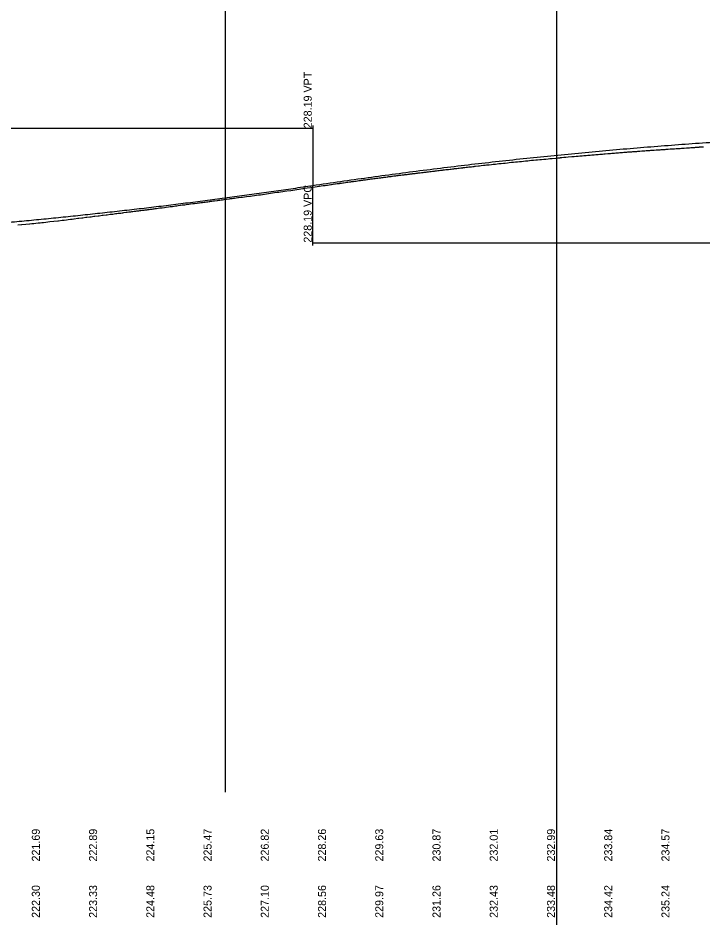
# Model space of a CAD drawing. Extents: x 1838386 to 1955906, y 719739 to 834437.
# Drawn here: x 1889393 to 1889991, y 825634 to 826420 of the extents above; entities that cross this region are included whole.
import ezdxf

# ---------------------------------------------------------------- set-up
doc = ezdxf.new("R2010")
doc.units = 0
for name, color, linetype in [('RD_DDB_Profile_EX', 7, 'Continuous'), ('RD_DDB_Profile_PR', 7, 'Continuous'), ('RD_DDB_StripGrade', 7, 'Continuous'), ('RD_DDB_VCLbl', 7, 'Continuous'), ('RD_Sketch1', 7, 'Continuous')]:
    doc.layers.add(name, color=color, linetype=linetype)

msp = doc.modelspace()

# ---------------------------------------------------------------- linework, layer by layer
at = {"layer": 'RD_DDB_Profile_EX'}
for points in [[(1889922.29, 826303.05), (1889923.03, 826303.09), (1889923.83, 826303.17), (1889924.77, 826303.24), (1889925.8, 826303.32), (1889926.43, 826303.36), (1889927.02, 826303.41), (1889928.21, 826303.49), (1889929.3, 826303.58), (1889930.04, 826303.62), (1889930.84, 826303.7), (1889931.82, 826303.77), (1889932.81, 826303.85), (1889933.58, 826303.89), (1889934.33, 826303.96), (1889935.32, 826304.02), (1889936.31, 826304.1), (1889937.85, 826304.21), (1889938.88, 826304.28), (1889939.82, 826304.35), (1889940.71, 826304.39), (1889941.67, 826304.49), (1889942.46, 826304.55), (1889943.33, 826304.61), (1889944.87, 826304.72), (1889945.89, 826304.79), (1889946.84, 826304.85), (1889947.73, 826304.9), (1889948.7, 826304.99), (1889950.36, 826305.11), (1889951.22, 826305.14), (1889951.96, 826305.21), (1889953.85, 826305.34), (1889954.76, 826305.38), (1889955.75, 826305.48), (1889956.56, 826305.53), (1889957.36, 826305.58), (1889958.32, 826305.62), (1889959.27, 826305.71), (1889960.07, 826305.76), (1889960.86, 826305.82), (1889962.82, 826305.95), (1889963.63, 826306.01), (1889964.37, 826306.05), (1889966.47, 826306.2), (1889967.88, 826306.28), (1889968.88, 826306.33), (1889969.89, 826306.42), (1889970.68, 826306.47), (1889971.38, 826306.52), (1889972.51, 826306.56), (1889973.76, 826306.68), (1889974.3, 826306.71), (1889974.89, 826306.75), (1889976.99, 826306.89), (1889977.72, 826306.94), (1889978.39, 826306.99), (1889979.57, 826307.04), (1889980.86, 826307.17), (1889981.36, 826307.21), (1889981.9, 826307.24), (1889984.1, 826307.38), (1889984.79, 826307.44), (1889985.41, 826307.47), (1889986.63, 826307.52), (1889987.99, 826307.65), (1889988.43, 826307.69), (1889988.91, 826307.71), (1889991.23, 826307.87), (1889991.85, 826307.92)], [(1889790.31, 826290.6), (1889791.5, 826290.77), (1889792.05, 826290.84), (1889792.55, 826290.89), (1889795.27, 826291.21), (1889795.67, 826291.25), (1889796.04, 826291.29), (1889797.5, 826291.41), (1889799.55, 826291.68), (1889800.96, 826291.8), (1889802.24, 826291.97), (1889802.67, 826292.02), (1889803.06, 826292.06), (1889804.49, 826292.18), (1889806.56, 826292.45), (1889808.05, 826292.57), (1889810.07, 826292.82), (1889811.54, 826292.94), (1889813, 826293.13), (1889813.58, 826293.19), (1889815.13, 826293.32), (1889817.08, 826293.57), (1889818.69, 826293.69), (1889820.59, 826293.92), (1889822.18, 826294.05), (1889824.09, 826294.29), (1889825.76, 826294.4), (1889827.61, 826294.64), (1889829.24, 826294.77), (1889831.11, 826295), (1889832.75, 826295.12), (1889834.62, 826295.35), (1889836.36, 826295.48), (1889838.31, 826295.71), (1889839.89, 826295.84), (1889841.63, 826296.04), (1889843.38, 826296.17), (1889845.27, 826296.39), (1889846.95, 826296.51), (1889848.74, 826296.71), (1889850.44, 826296.85), (1889852.22, 826297.06), (1889854.01, 826297.19), (1889856.01, 826297.41), (1889857.59, 826297.52), (1889859.49, 826297.73), (1889862.68, 826298.03), (1889862.98, 826298.05), (1889864.65, 826298.2), (1889866.47, 826298.35), (1889866.79, 826298.39), (1889868.16, 826298.48), (1889869.94, 826298.66), (1889871.64, 826298.78), (1889873.74, 826299), (1889876.7, 826299.25), (1889877.25, 826299.3), (1889878.71, 826299.4), (1889880.71, 826299.59), (1889882.27, 826299.71), (1889883.71, 826299.85), (1889884.1, 826299.88), (1889884.51, 826299.92), (1889885.86, 826300.02), (1889887.22, 826300.15), (1889887.6, 826300.17), (1889887.97, 826300.22), (1889889.35, 826300.33), (1889890.72, 826300.46), (1889891.46, 826300.53), (1889892.91, 826300.62), (1889894.24, 826300.76), (1889894.73, 826300.79), (1889895.27, 826300.85), (1889896.44, 826300.94), (1889897.74, 826301.06), (1889898.11, 826301.09), (1889898.44, 826301.12), (1889899.9, 826301.23), (1889901.25, 826301.36), (1889901.73, 826301.39), (1889902.25, 826301.45), (1889903.55, 826301.55), (1889904.75, 826301.65), (1889905.97, 826301.74), (1889908.25, 826301.94), (1889908.74, 826301.97), (1889909.23, 826302.02), (1889910.55, 826302.11), (1889911.77, 826302.22), (1889912.38, 826302.26), (1889913.03, 826302.33), (1889914.15, 826302.41), (1889915.27, 826302.51), (1889915.9, 826302.54), (1889916.5, 826302.6), (1889917.64, 826302.68), (1889918.79, 826302.79), (1889920.02, 826302.88), (1889921.2, 826302.96), (1889922.29, 826303.05)], [(1889701.99, 826279.82), (1889702.62, 826279.92), (1889703.74, 826280.07), (1889704.86, 826280.23), (1889705.5, 826280.3), (1889706.14, 826280.39), (1889707.3, 826280.54), (1889708.37, 826280.67), (1889709.13, 826280.75), (1889709.96, 826280.88), (1889710.87, 826281), (1889711.87, 826281.13), (1889712.54, 826281.2), (1889713.15, 826281.29), (1889714.32, 826281.44), (1889715.39, 826281.58), (1889716.15, 826281.66), (1889716.98, 826281.79), (1889717.89, 826281.91), (1889718.89, 826282.04), (1889719.57, 826282.11), (1889720.18, 826282.2), (1889721.34, 826282.35), (1889722.4, 826282.48), (1889723.16, 826282.55), (1889724, 826282.68), (1889724.95, 826282.8), (1889725.91, 826282.93), (1889726.71, 826283.01), (1889727.5, 826283.13), (1889728.45, 826283.25), (1889729.41, 826283.37), (1889730.21, 826283.44), (1889731.01, 826283.56), (1889732.01, 826283.68), (1889732.92, 826283.79), (1889733.84, 826283.88), (1889734.85, 826284.03), (1889735.6, 826284.12), (1889736.43, 826284.22), (1889737.27, 826284.3), (1889738.03, 826284.42), (1889739.02, 826284.54), (1889739.94, 826284.65), (1889740.85, 826284.73), (1889741.85, 826284.88), (1889742.65, 826284.98), (1889743.44, 826285.07), (1889744.4, 826285.16), (1889745.35, 826285.3), (1889746.15, 826285.4), (1889746.95, 826285.5), (1889747.91, 826285.59), (1889748.86, 826285.73), (1889749.69, 826285.83), (1889750.45, 826285.92), (1889751.52, 826286.02), (1889752.69, 826286.2), (1889753.29, 826286.27), (1889753.96, 826286.35), (1889754.97, 826286.44), (1889755.88, 826286.57), (1889756.71, 826286.67), (1889757.47, 826286.76), (1889758.54, 826286.86), (1889759.7, 826287.04), (1889760.34, 826287.12), (1889760.97, 826287.19), (1889762.09, 826287.3), (1889763.19, 826287.47), (1889763.84, 826287.55), (1889764.49, 826287.62), (1889765.59, 826287.72), (1889766.7, 826287.88), (1889767.37, 826287.97), (1889767.99, 826288.03), (1889769.2, 826288.14), (1889770.51, 826288.33), (1889770.98, 826288.39), (1889771.49, 826288.44), (1889772.65, 826288.54), (1889773.7, 826288.7), (1889774.37, 826288.78), (1889775, 826288.85), (1889776.2, 826288.96), (1889777.51, 826289.15), (1889778.01, 826289.21), (1889778.51, 826289.27), (1889779.76, 826289.39), (1889780.99, 826289.56), (1889781.5, 826289.62), (1889782.01, 826289.67), (1889783.25, 826289.79), (1889784.49, 826289.97), (1889785.03, 826290.03), (1889785.52, 826290.09), (1889786.86, 826290.21), (1889788.3, 826290.41), (1889788.64, 826290.45), (1889789.02, 826290.49), (1889790.31, 826290.6)], [(1889567.27, 826261.03), (1889568.1, 826261.14), (1889569.34, 826261.27), (1889570.49, 826261.46), (1889571.06, 826261.54), (1889571.58, 826261.61), (1889572.94, 826261.76), (1889574.28, 826261.97), (1889575.11, 826262.08), (1889577.78, 826262.45), (1889578.62, 826262.56), (1889579.96, 826262.69), (1889581.3, 826262.9), (1889582.12, 826263), (1889585.13, 826263.4), (1889585.63, 826263.47), (1889588.32, 826263.82), (1889588.75, 826263.88), (1889589.14, 826263.93), (1889592.64, 826264.39), (1889595.64, 826264.78), (1889596.15, 826264.85), (1889597.65, 826265.02), (1889599.66, 826265.33), (1889603.16, 826265.81), (1889604.73, 826265.98), (1889606.67, 826266.29), (1889610.18, 826266.78), (1889613.68, 826267.28), (1889615.34, 826267.48), (1889617.19, 826267.77), (1889619.39, 826268.08), (1889620.82, 826268.28), (1889622.43, 826268.48), (1889624.21, 826268.76), (1889625.94, 826268.98), (1889627.83, 826269.29), (1889631.32, 826269.79), (1889633.03, 826270.01), (1889634.83, 826270.29), (1889636.6, 826270.52), (1889638.65, 826270.84), (1889640.12, 826271.03), (1889641.83, 826271.31), (1889645.65, 826271.86), (1889649.15, 826272.38), (1889650.71, 826272.58), (1889652.65, 826272.88), (1889654.28, 826273.1), (1889655.77, 826273.33), (1889656.1, 826273.38), (1889656.47, 826273.44), (1889657.8, 826273.62), (1889659.64, 826273.91), (1889661.28, 826274.12), (1889662.79, 826274.35), (1889663.11, 826274.39), (1889663.46, 826274.45), (1889664.87, 826274.64), (1889666.29, 826274.86), (1889666.62, 826274.9), (1889666.95, 826274.95), (1889668.37, 826275.14), (1889669.79, 826275.36), (1889670.13, 826275.4), (1889670.46, 826275.45), (1889671.94, 826275.65), (1889673.3, 826275.86), (1889673.77, 826275.91), (1889674.27, 826276), (1889675.48, 826276.15), (1889676.81, 826276.36), (1889677.15, 826276.4), (1889677.45, 826276.45), (1889678.95, 826276.64), (1889680.32, 826276.85), (1889680.78, 826276.9), (1889681.27, 826276.99), (1889682.55, 826277.16), (1889683.83, 826277.34), (1889684.3, 826277.4), (1889684.76, 826277.47), (1889686.05, 826277.64), (1889687.34, 826277.83), (1889687.81, 826277.89), (1889688.27, 826277.96), (1889689.62, 826278.14), (1889690.84, 826278.32), (1889691.44, 826278.39), (1889692.1, 826278.5), (1889693.17, 826278.63), (1889694.34, 826278.8), (1889694.84, 826278.86), (1889695.29, 826278.93), (1889696.62, 826279.1), (1889697.85, 826279.28), (1889698.45, 826279.35), (1889699.11, 826279.46), (1889700.24, 826279.6), (1889701.36, 826279.75), (1889701.99, 826279.82)], [(1889440.38, 826244.71), (1889441.84, 826244.92), (1889442.21, 826244.96), (1889445.35, 826245.35), (1889446.02, 826245.43), (1889448.86, 826245.78), (1889449.5, 826245.87), (1889452.37, 826246.23), (1889452.99, 826246.31), (1889455.88, 826246.68), (1889456.81, 826246.79), (1889459.38, 826247.12), (1889459.98, 826247.19), (1889462.89, 826247.55), (1889463.32, 826247.59), (1889463.79, 826247.66), (1889466.39, 826247.97), (1889467.26, 826248.08), (1889469.9, 826248.4), (1889470.75, 826248.51), (1889473.41, 826248.83), (1889474.55, 826248.98), (1889475.71, 826249.11), (1889476.92, 826249.28), (1889478.03, 826249.42), (1889479.22, 826249.55), (1889480.42, 826249.71), (1889481.53, 826249.85), (1889482.78, 826249.99), (1889483.93, 826250.15), (1889484.61, 826250.22), (1889485.34, 826250.33), (1889487.43, 826250.6), (1889488.51, 826250.73), (1889489.78, 826250.87), (1889490.94, 826251.04), (1889491.6, 826251.11), (1889492.31, 826251.22), (1889493.38, 826251.34), (1889494.45, 826251.48), (1889495.8, 826251.64), (1889496.87, 826251.77), (1889497.96, 826251.92), (1889498.63, 826251.99), (1889499.29, 826252.09), (1889500.42, 826252.23), (1889501.47, 826252.36), (1889502.25, 826252.44), (1889503.1, 826252.57), (1889503.99, 826252.69), (1889504.94, 826252.81), (1889505.7, 826252.89), (1889506.5, 826253.01), (1889507.53, 826253.14), (1889508.48, 826253.26), (1889509.28, 826253.34), (1889510.07, 826253.47), (1889511.06, 826253.59), (1889511.98, 826253.72), (1889512.89, 826253.81), (1889513.88, 826253.96), (1889515.49, 826254.18), (1889517.04, 826254.38), (1889518.06, 826254.5), (1889519, 826254.63), (1889520.85, 826254.87), (1889522.51, 826255.1), (1889524.33, 826255.35), (1889526.01, 826255.57), (1889526.92, 826255.67), (1889527.83, 826255.81), (1889529.52, 826256.04), (1889530.54, 826256.15), (1889531.65, 826256.33), (1889533.03, 826256.51), (1889534.82, 826256.75), (1889536.53, 826256.99), (1889537.54, 826257.1), (1889538.64, 826257.27), (1889540.04, 826257.46), (1889542.14, 826257.73), (1889543.55, 826257.91), (1889545.63, 826258.17), (1889547.05, 826258.35), (1889549.44, 826258.68), (1889550.56, 826258.83), (1889551.65, 826258.95), (1889552.73, 826259.12), (1889553.42, 826259.21), (1889554.03, 826259.28), (1889555.25, 826259.41), (1889556.44, 826259.59), (1889557.58, 826259.74), (1889558.76, 826259.86), (1889559.95, 826260.05), (1889560.52, 826260.13), (1889561.09, 826260.2), (1889562.33, 826260.34), (1889563.45, 826260.52), (1889564.59, 826260.67), (1889567.27, 826261.03)], [(1889392.76, 826239.61), (1889395.94, 826239.91), (1889396.25, 826239.93), (1889399.77, 826240.26), (1889402.91, 826240.55), (1889403.27, 826240.58), (1889404.98, 826240.7), (1889406.78, 826240.93), (1889408.54, 826241.06), (1889410.49, 826241.3), (1889412.46, 826241.52), (1889413.78, 826241.66), (1889415.29, 826241.83), (1889417.46, 826242.06), (1889420.95, 826242.44), (1889424.45, 826242.84), (1889427.82, 826243.23), (1889428.26, 826243.28), (1889431.44, 826243.66), (1889433.23, 826243.83), (1889435.25, 826244.11), (1889436.79, 826244.27), (1889438.82, 826244.55), (1889440.38, 826244.71)]]:
    msp.add_lwpolyline(points, dxfattribs=at)
at = {"layer": 'RD_DDB_Profile_PR'}
for points in [[(1889650.58, 826274.06), (1889674.68, 826277.6), (1889698.78, 826281), (1889722.88, 826284.27), (1889746.98, 826287.4), (1889771.08, 826290.39), (1889795.18, 826293.24), (1889819.28, 826295.95), (1889843.38, 826298.53), (1889867.48, 826300.97), (1889891.58, 826303.27), (1889915.68, 826305.44), (1889939.78, 826307.47), (1889963.88, 826309.35), (1889987.98, 826311.11), (1890012.08, 826312.72), (1890036.18, 826314.19), (1890060.28, 826315.53), (1890084.38, 826316.73), (1890108.48, 826317.79), (1890132.58, 826318.72), (1890156.68, 826319.51), (1890180.78, 826320.16), (1890204.88, 826320.67), (1890228.98, 826321.04), (1890253.08, 826321.28), (1890277.18, 826321.38), (1890301.28, 826321.34), (1890325.38, 826321.16), (1890349.48, 826320.85), (1890373.58, 826320.39), (1890397.68, 826319.8), (1890421.78, 826319.07), (1890445.88, 826318.21), (1890469.98, 826317.21), (1890494.08, 826316.06), (1890518.18, 826314.79), (1890542.28, 826313.37), (1890566.38, 826311.81), (1890590.48, 826310.12), (1890614.58, 826308.29), (1890638.68, 826306.33), (1890662.78, 826304.22), (1890686.88, 826301.98), (1890710.98, 826299.6), (1890735.08, 826297.08), (1890759.18, 826294.42), (1890783.28, 826291.63), (1890807.38, 826288.7), (1890831.48, 826285.63), (1890855.58, 826282.42)], [(1888795.58, 826225.22), (1888812.68, 826224.64), (1888829.78, 826224.13), (1888846.88, 826223.68), (1888863.98, 826223.29), (1888881.08, 826222.97), (1888898.18, 826222.71), (1888915.28, 826222.51), (1888932.38, 826222.38), (1888949.48, 826222.31), (1888966.58, 826222.31), (1888983.68, 826222.36), (1889000.78, 826222.48), (1889017.88, 826222.67), (1889034.98, 826222.92), (1889052.08, 826223.23), (1889069.18, 826223.6), (1889086.28, 826224.04), (1889103.38, 826224.54), (1889120.48, 826225.11), (1889137.58, 826225.73), (1889154.68, 826226.42), (1889171.78, 826227.18), (1889188.88, 826228), (1889205.98, 826228.88), (1889223.08, 826229.82), (1889240.18, 826230.83), (1889257.28, 826231.91), (1889274.38, 826233.04), (1889291.48, 826234.24), (1889308.58, 826235.5), (1889325.68, 826236.83), (1889342.78, 826238.22), (1889359.88, 826239.67), (1889376.98, 826241.18), (1889394.08, 826242.76), (1889411.18, 826244.4), (1889428.28, 826246.11), (1889445.38, 826247.88), (1889462.48, 826249.71), (1889479.58, 826251.61), (1889496.68, 826253.57), (1889513.78, 826255.59), (1889530.88, 826257.68), (1889547.98, 826259.83), (1889565.08, 826262.04), (1889582.18, 826264.32), (1889599.28, 826266.66), (1889616.38, 826269.06), (1889633.48, 826271.53), (1889650.58, 826274.06)]]:
    msp.add_spline(points, degree=3, dxfattribs=at)
at = {"layer": 'RD_DDB_VCLbl'}
for p, q in [((1888795.58, 826324.06), (1889650.58, 826324.06)), ((1889650.58, 826326.56), (1889650.58, 826274.06)), ((1889650.58, 826221.56), (1889650.58, 826274.06)), ((1889650.58, 826224.06), (1890855.58, 826224.06))]:
    msp.add_line(p, q, dxfattribs=at)
at = {"layer": 'RD_Sketch1'}
for p, q in [((1889863.35, 827957.8), (1889863.35, 821246.49)), ((1889574.15, 825743.65), (1889574.15, 827268.63))]:
    msp.add_line(p, q, dxfattribs=at)

# ---------------------------------------------------------------- texts
at = {"layer": 'RD_DDB_StripGrade'}
for s, p in [('228.19 VPT', (1889649.58, 826324.06)), ('228.19 VPC', (1889649.58, 826224.06)), ('221.69', (1889412.08, 825683.11)), ('222.89', (1889462.08, 825683.11)), ('224.15', (1889512.08, 825683.11)), ('225.47', (1889562.08, 825683.11)), ('226.82', (1889612.08, 825683.11)), ('228.26', (1889662.08, 825683.11)), ('229.63', (1889712.08, 825683.11)), ('230.87', (1889762.08, 825683.11)), ('232.01', (1889812.08, 825683.11)), ('232.99', (1889862.08, 825683.11)), ('233.84', (1889912.08, 825683.11)), ('234.57', (1889962.08, 825683.11)), ('222.30', (1889412.08, 825633.86)), ('223.33', (1889462.08, 825633.86)), ('224.48', (1889512.08, 825633.86)), ('225.73', (1889562.08, 825633.86)), ('227.10', (1889612.08, 825633.86)), ('228.56', (1889662.08, 825633.86)), ('229.97', (1889712.08, 825633.86)), ('231.26', (1889762.08, 825633.86)), ('232.43', (1889812.08, 825633.86)), ('233.48', (1889862.08, 825633.86)), ('234.42', (1889912.08, 825633.86)), ('235.24', (1889962.08, 825633.86))]:
    msp.add_text(s, height=7, rotation=90, dxfattribs=at).set_placement(p)

doc.saveas('drawing.dxf')
